// Mitsubishi GX Works2 project: MM-11MR-2MTS-FE700-FX-A   PLC: FX1S

PROGRAM MAIN
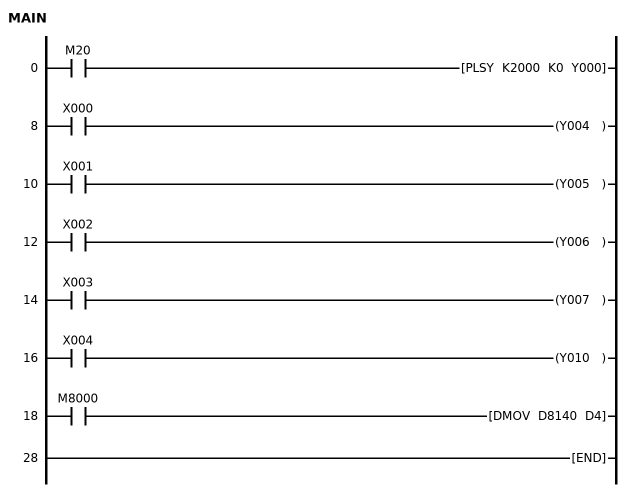
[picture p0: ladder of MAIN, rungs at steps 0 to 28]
0     LD      M20
      PLSY    K2000 K0 Y000
8     LD      X000
      OUT     Y004
10    LD      X001
      OUT     Y005
12    LD      X002
      OUT     Y006
14    LD      X003
      OUT     Y007
16    LD      X004
      OUT     Y010
18    LD      M8000
      DMOV    D8140 D4
28    END
END_PROGRAM
